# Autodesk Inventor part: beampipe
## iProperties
Shininess: 64.0
Length Units: 11269
Angle Units: 11279
Time Units: 11290
Mass Units: 11283
Length Display Precision: 3
Angle Display Precision: 2
Compacted: True
Part Number: beampipe
Document SubType Name: Modeling
Created: 2004-07
Designer: Peter
Manufacturer: Standard
Standards Organization: Custom
Density: 0.0
Volumn: 0.0
Area: 0.0
PropertySet Name: Model Information
Control State: 0
Master: False
Checked Out: False
Author: Peter
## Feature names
1. Revolution1
